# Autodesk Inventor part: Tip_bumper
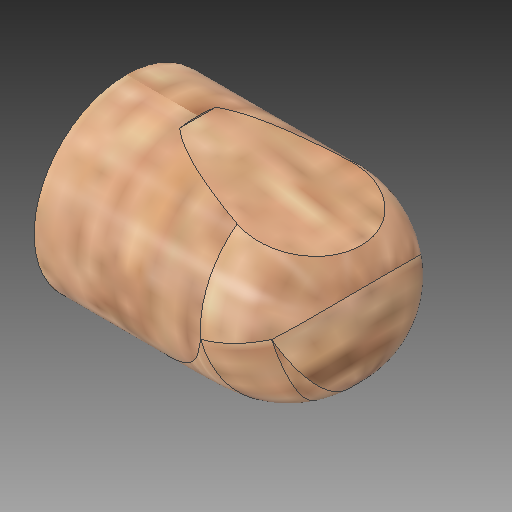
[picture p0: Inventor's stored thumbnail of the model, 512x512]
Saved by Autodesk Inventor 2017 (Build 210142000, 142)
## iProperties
Created: 2017-05
Part Number: Tip_bumper
Material: Generic
Document SubType Name: Modeling
Designer: alez_
Density: 1 g/cm^3
Appearance: Birch - Natural Polished
Author: alez_
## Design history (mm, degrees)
sketch "Sketch1"
  geometry: C1 r 4.5 at (0, 0); C2 r 7.5 at (0, 0); 1 further point
  constraints: 2 centre point, 2 coincident
  dimensions: "d0" = 9 diameter of C1; "d1" = 15 diameter of C2
extrude "Extrusion1" new body sketch "Sketch1" distance "d2" = 1; taper "d3" = 0 deg
sketch "Sketch2"
  geometry: C1 r 5.5 at (0, 0); C2 r 7.5 at (0, 0); 1 further point
  constraints: 2 centre point, 2 coincident
  dimensions: "d4" = 11 diameter of C1
extrude "Extrusion2" join sketch "Sketch2" distance "d5" = 4.5; taper "d6" = 0 deg
sketch "Sketch3"
  geometry: C1 r 4.5 at (0, 0) reference; C2 r 7.5 at (0, 0); 1 further point
  constraints: 1 centre point, 1 coincident
extrude "Extrusion3" join sketch "Sketch3" distance "d7" = 15.5; taper "d8" = 0 deg
fillet "Fillet1" dims "d9" = 7.5
workplane "Work Plane3"
sketch "Sketch5"
  geometry: L1 (20.348, -3.059)-(18.695, -5.168); L2 (18.695, -5.168)-(17.044, -6.417); L3 (17.044, -6.417)-(14.768, -7.265); L4 (14.768, -7.265)-(11.637, -7.265); L5 (11.637, -7.265)-(4.126, -7.5); L6 (20.348, -3.059)-(20.348, -7.868); L7 (20.348, -7.868)-(4.126, -7.868); L8 (4.126, -7.868)-(4.126, -7.5); 1 further point
  constraints: 6 end point, 2 perpendicular, 1 horizontal, 1 vertical, 3 other
extrude "Extrusion4" cut sketch "Sketch5" distance "d12" = 15.5; taper "d13" = 0 deg
fillet "Fillet2" dims "d14" = 7
sketch "Sketch6"
  geometry: C1 r 5.5 at (0, 0); 1 further point
  constraints: 1 centre point, 1 coincident
extrude "Extrusion5" cut sketch "Sketch6" distance "d15" = 5; taper "d16" = 0 deg
fillet "Fillet3" dims "d17" = 4
workplane "Work Plane7"
  workplane "Work Plane6"
sketch "Sketch8"
  geometry: L1 (7.301, -4.422)-(5.301, -4.422); L2 (5.301, -4.422)-(5.301, -15.974); L3 (5.301, -15.974)-(5.301, -19.422); L4 (5.301, -19.422)-(-5.5, -19.422); L5 (-5.5, -19.422)-(-5.5, -4.422); L6 (-5.5, -4.422)-(-7.5, -4.422); L7 (-7.5, 0)-(-7.5, -13.295) reference; L8 (5.301, -4.422)-(-5.5, -4.422); 4 further points; 1 other entity
  constraints: 14 end point, 4 point on line, 3 perpendicular, 2 horizontal, 1 other
  dimensions: "d24" = 2 distance of L1.start L1.end; "d25" = 2 distance of L5.end L6.end; "d28" = 15 distance of L4.end L5.end
extrude "Extrusion7" cut sketch "Sketch8" distance "d26" = 2; taper "d27" = 0 deg
body "Solid1"
other parameters: "d11" = -8, "d22" = 170 deg, "d23" = -10.25
